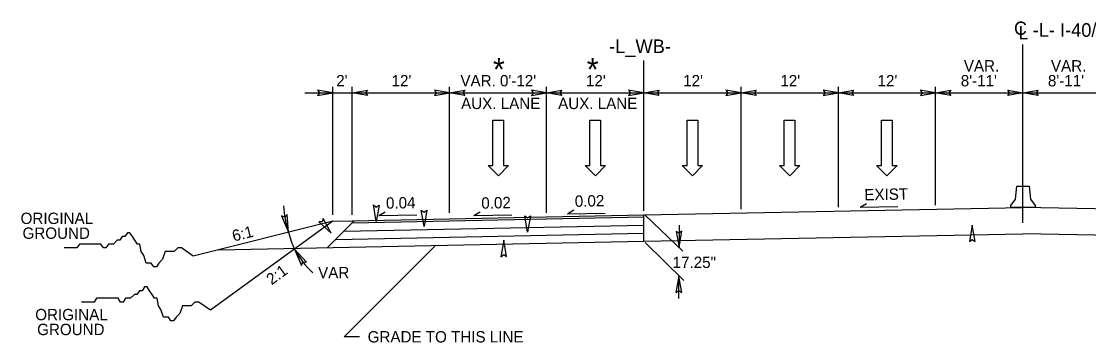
# Model space of a CAD drawing. Extents: x 1725232 to 1728895, y 538685 to 540544.
# Drawn here: x 1726942 to 1727602, y 540346 to 540544 of the extents above; entities that cross this region are included whole.
import ezdxf

# ---------------------------------------------------------------- set-up
doc = ezdxf.new("R2010")
doc.units = 0
for name, color, linetype in [('Default', 7, 'Continuous'), ('Prop Dimension Text', 7, 'Continuous'), ('Typical Hinge Slope Interstate CELL', 7, 'Continuous'), ('Typical Pavement Slope CELL', 7, 'Continuous'), ('Typical Pavement Slope Information CELL', 7, 'Continuous'), ('Typical Terminator CELL', 7, 'Continuous'), ('Typical Text Centerline CELL', 7, 'Continuous'), ('Typical Text General CELL', 7, 'Continuous')]:
    doc.layers.add(name, color=color, linetype=linetype)

msp = doc.modelspace()

# ---------------------------------------------------------------- linework, layer by layer
at = {"layer": 'Default'}
for p, q in [((1727326.84, 540427.18), (1727326.84, 540520.09)), ((1727117.43, 540500.07), (1727146.8, 540500.07)), ((1727134.69, 540424.78), (1727134.69, 540503.77)), ((1727146.69, 540424.78), (1727146.69, 540503.77)), ((1727146.69, 540424.78), (1727146.69, 540502.57)), ((1727146.8, 540500.07), (1727206.85, 540500.07)), ((1727206.85, 540425.98), (1727206.85, 540503.77)), ((1727206.96, 540500.07), (1727267.01, 540500.07)), ((1727266.79, 540425.98), (1727266.79, 540503.77)), ((1727266.9, 540500.07), (1727326.94, 540500.07)), ((1727326.84, 540427.18), (1727326.84, 540503.77)), ((1727326.94, 540500.07), (1727386.99, 540500.07)), ((1727386.88, 540428.38), (1727386.88, 540503.77)), ((1727386.99, 540500.07), (1727447.04, 540500.07)), ((1727447.04, 540429.59), (1727447.04, 540503.77)), ((1727447.04, 540500.07), (1727507.09, 540500.07)), ((1727507.09, 540430.79), (1727507.09, 540503.77)), ((1727507.09, 540500.07), (1727561.09, 540500.07)), ((1727561.09, 540500.07), (1727615.29, 540500.07)), ((1727233.58, 540455.17), (1727233.58, 540483.17)), ((1727233.58, 540483.17), (1727240.18, 540483.17)), ((1727240.18, 540483.17), (1727240.18, 540455.17)), ((1727293.52, 540455.17), (1727293.52, 540483.17)), ((1727293.52, 540483.17), (1727300.12, 540483.17)), ((1727300.12, 540483.17), (1727300.12, 540455.17)), ((1727353.57, 540455.17), (1727353.57, 540483.17)), ((1727353.57, 540483.17), (1727360.17, 540483.17)), ((1727360.17, 540483.17), (1727360.17, 540455.17)), ((1727413.62, 540455.17), (1727413.62, 540483.17)), ((1727413.62, 540483.17), (1727420.22, 540483.17)), ((1727420.22, 540483.17), (1727420.22, 540455.17)), ((1727473.66, 540455.17), (1727473.66, 540483.17)), ((1727473.66, 540483.17), (1727480.26, 540483.17)), ((1727480.26, 540483.17), (1727480.26, 540455.17)), ((1727236.98, 540448.87), (1727230.58, 540455.17)), ((1727230.58, 540455.17), (1727233.58, 540455.17)), ((1727243.18, 540455.17), (1727236.98, 540448.87)), ((1727240.18, 540455.17), (1727243.18, 540455.17)), ((1727296.92, 540448.87), (1727290.52, 540455.17)), ((1727290.52, 540455.17), (1727293.52, 540455.17)), ((1727303.12, 540455.17), (1727296.92, 540448.87)), ((1727300.12, 540455.17), (1727303.12, 540455.17)), ((1727356.97, 540448.87), (1727350.57, 540455.17)), ((1727350.57, 540455.17), (1727353.57, 540455.17)), ((1727363.17, 540455.17), (1727356.97, 540448.87)), ((1727360.17, 540455.17), (1727363.17, 540455.17)), ((1727417.02, 540448.87), (1727410.62, 540455.17)), ((1727410.62, 540455.17), (1727413.62, 540455.17)), ((1727423.22, 540455.17), (1727417.02, 540448.87)), ((1727420.22, 540455.17), (1727423.22, 540455.17)), ((1727477.06, 540448.87), (1727470.66, 540455.17)), ((1727470.66, 540455.17), (1727473.66, 540455.17)), ((1727483.26, 540455.17), (1727477.06, 540448.87)), ((1727480.26, 540455.17), (1727483.26, 540455.17)), ((1727327.66, 540424.6), (1727350.96, 540402.3)), ((1727348.61, 540418.3), (1727348.61, 540404.54)), ((1727327.66, 540407.66), (1727351.49, 540384.17)), ((1727348.49, 540373.13), (1727348.49, 540386.89))]:
    msp.add_line(p, q, dxfattribs=at)
for points in [[(1727125.31, 540498.46), (1727134.69, 540500.07), (1727125.25, 540501.74), (1727126.45, 540500.07)], [(1727156.07, 540498.46), (1727146.69, 540500.07), (1727156.13, 540501.74), (1727154.93, 540500.07)], [(1727197.47, 540498.46), (1727206.85, 540500.07), (1727197.42, 540501.74), (1727198.62, 540500.07)], [(1727216.23, 540498.46), (1727206.85, 540500.07), (1727216.28, 540501.74), (1727215.08, 540500.07)], [(1727257.41, 540498.46), (1727266.79, 540500.07), (1727257.36, 540501.74), (1727258.56, 540500.07)], [(1727276.17, 540498.46), (1727266.79, 540500.07), (1727276.22, 540501.74), (1727275.02, 540500.07)], [(1727317.46, 540498.46), (1727326.84, 540500.07), (1727317.41, 540501.74), (1727318.6, 540500.07)], [(1727336.21, 540498.46), (1727326.84, 540500.07), (1727336.27, 540501.74), (1727335.07, 540500.07)], [(1727377.51, 540498.46), (1727386.88, 540500.07), (1727377.45, 540501.74), (1727378.65, 540500.07)], [(1727396.26, 540498.46), (1727386.88, 540500.07), (1727396.31, 540501.74), (1727395.12, 540500.07)], [(1727437.66, 540498.46), (1727447.04, 540500.07), (1727437.61, 540501.74), (1727438.81, 540500.07)], [(1727456.42, 540498.46), (1727447.04, 540500.07), (1727456.47, 540501.74), (1727455.27, 540500.07)], [(1727497.71, 540498.46), (1727507.09, 540500.07), (1727497.66, 540501.74), (1727498.85, 540500.07)], [(1727516.47, 540498.46), (1727507.09, 540500.07), (1727516.52, 540501.74), (1727515.32, 540500.07)], [(1727551.71, 540501.69), (1727561.09, 540500.07), (1727551.66, 540498.41), (1727552.85, 540500.07)], [(1727570.46, 540498.45), (1727561.09, 540500.07), (1727570.52, 540501.74), (1727569.32, 540500.07)], [(1727102.93, 540424.07), (1727107.38, 540414.04), (1727106.58, 540425.05), (1727105.06, 540423.24)], [(1727118.47, 540395.62), (1727110.94, 540403.59), (1727115.35, 540393.48), (1727116.19, 540395.69)], [(1727118.47, 540395.62), (1727110.94, 540403.59), (1727115.35, 540393.48), (1727116.19, 540395.69)]]:
    msp.add_lwpolyline(points, close=True, dxfattribs=at)
at = {"layer": 'Typical Hinge Slope Interstate CELL'}
for points in [[(1727048.47, 540399.31), (1727041.25, 540404.38), (1727038.91, 540404.38), (1727036.58, 540402.05), (1727035.02, 540402.05), (1727032.68, 540402.05), (1727031.13, 540402.05), (1727029.57, 540397.36), (1727027.23, 540395.04), (1727025.67, 540392.69), (1727024.11, 540392.69), (1727022.56, 540395.04), (1727021, 540395.04), (1727019.44, 540395.04), (1727017.89, 540399.71), (1727016.33, 540402.05), (1727015.55, 540406.73), (1727013.99, 540406.73), (1727012.43, 540409.05), (1727010.88, 540411.4), (1727009.32, 540413.74), (1727007.76, 540413.74), (1727006.2, 540411.4), (1727004.65, 540411.4), (1727003.09, 540409.05), (1727001.53, 540409.05), (1726999.19, 540406.73), (1726997.64, 540406.73), (1726996.08, 540406.73), (1726994.52, 540404.38), (1726992.96, 540404.38), (1726991.41, 540406.73), (1726989.85, 540406.73), (1726988.29, 540406.73), (1726986.74, 540406.73), (1726985.18, 540406.73), (1726982.84, 540406.73), (1726980.51, 540406.73), (1726978.17, 540406.73), (1726976.61, 540404.38), (1726974.28, 540404.38), (1726971.94, 540404.38), (1726968.82, 540404.38)], [(1727059.08, 540365.87), (1727051.86, 540370.94), (1727049.52, 540370.94), (1727047.19, 540368.61), (1727045.63, 540368.61), (1727043.29, 540368.61), (1727041.73, 540368.61), (1727040.18, 540363.92), (1727037.84, 540361.6), (1727036.28, 540359.25), (1727034.72, 540359.25), (1727033.17, 540361.6), (1727031.61, 540361.6), (1727030.05, 540361.6), (1727028.49, 540366.27), (1727026.94, 540368.61), (1727026.15, 540373.29), (1727024.6, 540373.29), (1727023.04, 540375.61), (1727021.48, 540377.96), (1727019.93, 540380.3), (1727018.37, 540380.3), (1727016.81, 540377.96), (1727015.25, 540377.96), (1727013.7, 540375.61), (1727012.14, 540375.61), (1727009.8, 540373.29), (1727008.24, 540373.29), (1727006.69, 540373.29), (1727005.13, 540370.94), (1727003.57, 540370.94), (1727002.01, 540373.29), (1727000.46, 540373.29), (1726998.9, 540373.29), (1726997.34, 540373.29), (1726995.79, 540373.29), (1726993.45, 540373.29), (1726991.11, 540373.29), (1726988.77, 540373.29), (1726987.22, 540370.94), (1726984.89, 540370.94), (1726982.55, 540370.94), (1726979.43, 540370.94)]]:
    msp.add_lwpolyline(points, dxfattribs=at)
for centre, start, end in [((1727164.55, 540433.38), 182.93426, 198.68598), ((1727163.68, 540432.93), 209.07785, 226.69411), ((1727163.68, 540432.93), 209.07785, 226.69411)]:
    msp.add_arc(centre, 60.35, start, end, dxfattribs=at)
msp.add_ellipse((1727136.27, 540448.47), major_axis=(-9.27, -59.64), ratio=0.5, start_param=5.403228, end_param=5.638322, dxfattribs=at)
at = {"layer": 'Typical Pavement Slope CELL'}
for p, q in [((1727556.5, 540434.5), (1727557.33, 540442.42)), ((1727557.33, 540442.42), (1727561.09, 540442.42)), ((1727561.09, 540442.42), (1727564.84, 540442.42)), ((1727564.84, 540442.42), (1727565.67, 540434.5)), ((1727553.59, 540430.63), (1727556.5, 540434.5)), ((1727565.67, 540434.5), (1727568.58, 540430.63)), ((1727326.84, 540424.71), (1727561.06, 540429.4)), ((1727553.59, 540429.38), (1727553.59, 540430.63)), ((1727568.58, 540429.38), (1727553.59, 540429.38)), ((1727795.33, 540424.71), (1727561.09, 540429.4)), ((1727568.58, 540430.63), (1727568.58, 540429.38)), ((1727134.69, 540420.87), (1727048.47, 540399.31)), ((1727134.69, 540420.87), (1727059.08, 540365.87)), ((1727147.97, 540421.13), (1727131.38, 540404.54)), ((1727134.69, 540420.87), (1727146.69, 540421.11)), ((1727146.69, 540421.11), (1727326.81, 540424.71)), ((1727146.69, 540419.86), (1727326.84, 540423.46)), ((1727326.84, 540408.45), (1727326.84, 540424.71)), ((1727136.48, 540409.65), (1727326.84, 540413.45)), ((1727141.59, 540414.75), (1727326.84, 540418.46)), ((1727326.84, 540408.45), (1727561.09, 540413.13)), ((1727795.33, 540408.45), (1727561.09, 540413.13)), ((1727063.98, 540403.19), (1727326.84, 540408.45))]:
    msp.add_line(p, q, dxfattribs=at)
at = {"layer": 'Typical Pavement Slope Information CELL'}
for p, q in [((1727163.21, 540424.28), (1727167.13, 540426.65)), ((1727221.91, 540424.28), (1727225.82, 540426.65)), ((1727279.67, 540425.43), (1727283.58, 540427.8)), ((1727279.67, 540425.43), (1727302.98, 540425.9)), ((1727460.45, 540429.46), (1727464.36, 540431.83)), ((1727460.45, 540429.46), (1727483.76, 540429.93)), ((1727163.21, 540424.28), (1727186.52, 540424.75)), ((1727221.91, 540424.28), (1727245.22, 540424.75))]:
    msp.add_line(p, q, dxfattribs=at)
at = {"layer": 'Typical Terminator CELL'}
for p, q in [((1727141.67, 540349.49), (1727198.13, 540405.87)), ((1727151.23, 540349.49), (1727141.67, 540349.49))]:
    msp.add_line(p, q, dxfattribs=at)
for points in [[(1727163.25, 540430.8), (1727161.52, 540420.75), (1727159.73, 540430.86), (1727161.52, 540429.57)], [(1727192.87, 540427.67), (1727191.14, 540417.63), (1727189.35, 540427.73), (1727191.14, 540426.45)], [(1727126.08, 540420.39), (1727133.59, 540413.5), (1727128.83, 540422.59), (1727128.2, 540420.48)], [(1727256.74, 540424.13), (1727255.01, 540414.09), (1727253.23, 540424.19), (1727255.01, 540422.9)], [(1727346.88, 540414.59), (1727348.61, 540404.54), (1727350.4, 540414.65), (1727348.61, 540413.36)], [(1727531.5, 540408.34), (1727529.77, 540418.38), (1727527.98, 540408.28), (1727529.77, 540409.56)], [(1727241.98, 540399), (1727240.25, 540409.05), (1727238.46, 540398.95), (1727240.25, 540400.23)], [(1727350.22, 540376.85), (1727348.49, 540386.89), (1727346.71, 540376.79), (1727348.49, 540378.07)]]:
    msp.add_lwpolyline(points, close=True, dxfattribs=at)
at = {"layer": 'Typical Text Centerline CELL'}
msp.add_line((1727561.09, 540419.94), (1727561.09, 540530.03), dxfattribs=at)

# ---------------------------------------------------------------- texts
at = {"layer": 'Default'}
msp.add_text('17.25"', height=7.005, dxfattribs=at).set_placement((1727344.65, 540391.97))
at = {"layer": 'Prop Dimension Text'}
for s, p in [('ORIGINAL', (1726941.82, 540419.13)), ('GROUND', (1726943, 540409.95)), ('VAR', (1727125.62, 540385.63)), ('ORIGINAL', (1726950.86, 540359.7)), ('GROUND', (1726952.04, 540350.52))]:
    msp.add_text(s, height=7.005, dxfattribs=at).set_placement(p)
for s, rotation, p in [('6:1', 14.03624, (1727073.49, 540408.25)), ('2:1', 36.02984, (1727096.88, 540381.21))]:
    msp.add_text(s, height=7.005, rotation=rotation, dxfattribs=at).set_placement(p)
at = {"layer": 'Typical Pavement Slope Information CELL'}
for s, height, p in [('*', 14.01, (1727233.63, 540507.58)), ('*', 14.01, (1727291.57, 540507.58)), ('VAR.', 7.005, (1727524.54, 540513.26)), ('VAR.', 7.005, (1727578.37, 540513.26)), ("2'", 7.005, (1727136.81, 540504.08)), ("12'", 7.005, (1727171.01, 540504.08)), ("VAR. 0'-12'", 7.0055, (1727213.51, 540504.08)), ("12'", 7.005, (1727291.11, 540504.08)), ("12'", 7.005, (1727351.16, 540504.08)), ("12'", 7.005, (1727411.2, 540504.08)), ("12'", 7.005, (1727471.25, 540504.08)), ("8'-11'", 7.005, (1727522.66, 540504.08)), ("8'-11'", 7.005, (1727576.49, 540504.07)), ('AUX. LANE', 7.005, (1727213.96, 540490.06)), ('AUX. LANE', 7.005, (1727273.9, 540490.06))]:
    msp.add_text(s, height=height, dxfattribs=at).set_placement(p)
for s, p in [('EXIST', (1727463.13, 540433.69)), ('0.04', (1727167.62, 540428.54)), ('0.02', (1727226.5, 540428.55)), ('0.02', (1727284.26, 540429.7))]:
    msp.add_text(s, height=7.005, rotation=1.14574, dxfattribs=at).set_placement(p)
at = {"layer": 'Typical Text Centerline CELL'}
for s, height, rotation, p in [('C', 8.2, 0.04425, (1727555.56, 540535.88)), ('L', 8.21, 359.99115, (1727558.29, 540533.08)), ('-L- I-40/US 311', 8.4214, 359.94168, (1727567.06, 540534.69))]:
    msp.add_text(s, height=height, rotation=rotation, dxfattribs=at).set_placement(p)
msp.add_text('-L_WB-', height=8.421, dxfattribs=at).set_placement((1727305.41, 540524.63))
at = {"layer": 'Typical Text General CELL'}
msp.add_text('GRADE TO THIS LINE', height=7.0055, rotation=360, dxfattribs=at).set_placement((1727156.23, 540345.98))

doc.saveas('drawing.dxf')
